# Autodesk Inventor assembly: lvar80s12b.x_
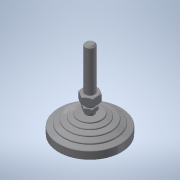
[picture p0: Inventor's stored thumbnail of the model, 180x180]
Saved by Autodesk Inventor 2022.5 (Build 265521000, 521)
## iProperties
Part Number: lvar80s12b.x_
Material: 一般
Document SubType Name: Assembly
Designer: ImaoCorp
Sending System: SOLIDWORKS 2017-2017317
MC: AMD64
MC_MODEL: Intel64 Family 6 Model 60 Stepping 3, GenuineIntel
OS: Windows_NT
FRU: Parasolid Version 29.0, build 201,  4-17-2017
FORMAT: text
GUISE: transmit
KEY: lvar80s12b
FILE: lvar80s12b.x_t
DATE: Mon Jul 01 18:15:50 2019
Author: ImaoCorp
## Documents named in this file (3)
- X:\14_SW2022-Inv2022\00_全2023-1023新製品(TCC)まで\l\lvar80s12b\LVAR80S12B.iam
- X:\14_SW2022-Inv2022\00_全2023-1023新製品(TCC)まで\l\lvar80s12b\lvar80s12b_01.ipt
- X:\14_SW2022-Inv2022\00_全2023-1023新製品(TCC)まで\l\lvar80s12b\lvar80s12b_02.ipt
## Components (2 placed, 2 different names)
1. lvar80s12b_01
2. lvar80s12b_02
